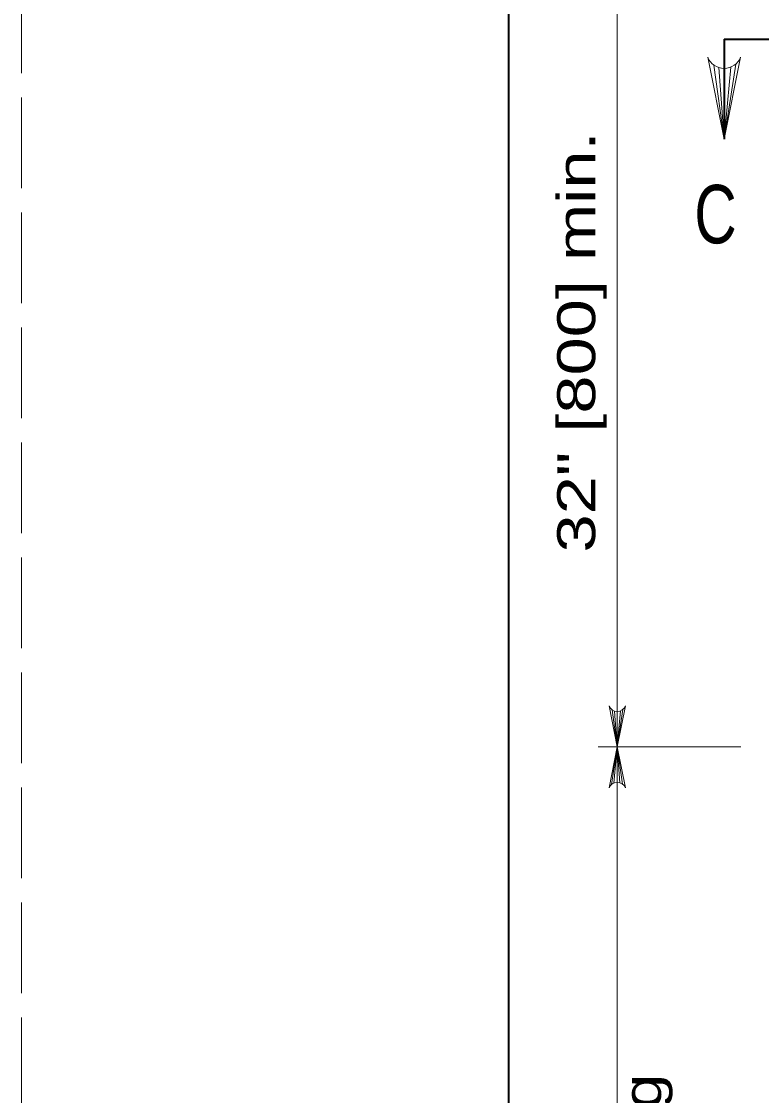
# Model space of a CAD drawing. Extents: x 1083.1 to 1117.1, y 697.4 to 719.4.
# Drawn here: x 1083.126 to 1086.164, y 710.538 to 714.946 of the extents above; entities that cross this region are included whole.
import ezdxf

# ---------------------------------------------------------------- set-up
doc = ezdxf.new("R2010")
doc.units = 0
doc.header["$LTSCALE"] = 0.062
doc.linetypes.add('LONG_DASHED', pattern=[7.5, 6, -1.5])
doc.layers.add('1', color=7, linetype='Continuous', lineweight=13)

msp = doc.modelspace()

# ---------------------------------------------------------------- linework, layer by layer
at = {"layer": '1'}
for p, q in [((1085.57192, 711.969), (1085.57192, 715.39908)), ((1085.96858, 714.76733), (1086.01117, 714.46275)), ((1085.98967, 714.757), (1086.01117, 714.46275)), ((1086.05825, 714.77092), (1086.01117, 714.46275)), ((1086.0385, 714.75925), (1086.01117, 714.46275)), ((1086.01117, 714.75392), (1086.01117, 714.46275)), ((1085.55058, 712.12133), (1085.57192, 711.969)), ((1085.56117, 712.11617), (1085.57192, 711.969)), ((1085.5955, 712.12308), (1085.57192, 711.969)), ((1085.58558, 712.11725), (1085.57192, 711.969)), ((1085.57192, 712.11458), (1085.57192, 711.969)), ((1086.0795, 711.969), (1085.49325, 711.969)), ((1085.54833, 711.81492), (1085.57192, 711.969)), ((1085.55825, 711.82075), (1085.57192, 711.969)), ((1085.57192, 708.15242), (1085.57192, 711.969)), ((1085.57192, 711.82342), (1085.57192, 711.969)), ((1085.58267, 711.82183), (1085.57192, 711.969)), ((1085.59325, 711.81667), (1085.57192, 711.969))]:
    msp.add_line(p, q, dxfattribs=at)
at = {"layer": '1', "lineweight": 35}
for p, q in [((1086.01117, 714.874), (1092.06975, 714.874)), ((1086.01117, 714.874), (1086.01117, 714.46275)), ((1086.01117, 714.72117), (1086.01117, 714.51567))]:
    msp.add_line(p, q, dxfattribs=at)
at = {"layer": '1', "linetype": 'LONG_DASHED'}
msp.add_lwpolyline([(1083.12642, 697.35408), (1117.12642, 697.35408), (1117.12642, 719.35408), (1083.12642, 719.35408)], close=True, dxfattribs=at)
at = {"layer": '1', "lineweight": 25}
msp.add_lwpolyline([(1116.62642, 697.85408), (1085.12642, 697.85408), (1085.12642, 718.85408)], dxfattribs=at)
at = {"layer": '1', "lineweight": 40}
msp.add_lwpolyline([(1085.12642, 718.85408), (1116.62642, 718.85408), (1116.62642, 697.85408), (1085.12642, 697.85408)], close=True, dxfattribs=at)
msp.add_lwpolyline([(1085.12642, 718.85408), (1116.62642, 718.85408), (1116.62642, 697.85408), (1085.12642, 697.85408)], close=True, dxfattribs=at)
at = {"layer": '1'}
for points in [[(1086.07842, 714.79917), (1086.01117, 714.46275), (1085.94383, 714.79917)], [(1085.60558, 712.13725), (1085.57192, 711.969), (1085.53825, 712.13725)], [(1085.53825, 711.80075), (1085.57192, 711.969), (1085.60558, 711.80075)]]:
    msp.add_lwpolyline(points, dxfattribs=at)
for centre, radius, start, end in [((1086.01109, 714.82638), 0.07261, 202.08782, 337.91395), ((1085.57188, 712.1508), 0.03631, 202.08782, 337.91395), ((1085.57195, 711.78719), 0.03631, 22.08782, 157.91395)]:
    msp.add_arc(centre, radius, start, end, dxfattribs=at)

# ---------------------------------------------------------------- texts
for s, width, p in [('32" [800] min.', 1.35, (1085.48158, 712.767)), ('step spacing', 1.25, (1085.75283, 709.1635))]:
    msp.add_text(s, height=0.156, rotation=90, dxfattribs=dict(at, width=width)).set_placement(p)
at = {"layer": '1', "width": 0.75}
msp.add_text('C', height=0.24, dxfattribs=at).set_placement((1085.8885, 714.0355))

doc.saveas('drawing.dxf')
